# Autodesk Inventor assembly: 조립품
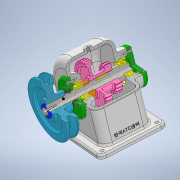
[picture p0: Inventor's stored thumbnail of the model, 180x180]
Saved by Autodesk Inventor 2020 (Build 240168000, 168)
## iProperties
Created: 2022-09
Part Number: 조립품
Document SubType Name: Assembly
Designer: Administrator
Author: Administrator
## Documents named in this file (16)
- C:\Users\Administrator\Desktop\720906V1025\조립품.iam
- C:\Users\Administrator\Desktop\720906V1025\본체.ipt
- C:\Users\Administrator\Desktop\720906V1025\축.ipt
- C:\Users\Administrator\Desktop\720906V1025\뒤커버.ipt
- C:\Users\Administrator\Desktop\720906V1025\베어링 6203.ipt
- C:\Users\Administrator\Desktop\720906V1025\스퍼기어.ipt
- C:\Users\Administrator\Desktop\720906V1025\앞커버.ipt
- C:\Users\Administrator\Desktop\720906V1025\오일 실 17 x 30 x 8.ipt
- C:\Users\Administrator\Desktop\720906V1025\칼라.ipt
- C:\Users\Administrator\Desktop\720906V1025\V-벨트풀리.ipt
- C:\Users\Administrator\Desktop\720906V1025\키 6 x 6 x 22.ipt
- C:\Users\Administrator\Desktop\720906V1025\키 5 x 5 x 18.ipt
- C:\Users\Administrator\Desktop\720906V1025\와셔 6 x 22.ipt
- C:\Users\Administrator\Desktop\720906V1025\육각머리볼트 M3 x 8.ipt
- C:\Users\Administrator\Desktop\720906V1025\멈춤나사 M4 x 10.ipt
- C:\Users\Administrator\Desktop\720906V1025\볼트 M3 x 10.ipt
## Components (9 placed, 2 different names)
1. V-벨트풀리:1 — 플러쉬:1
2. ISO 4762 M3 x 10:2
3. ISO 4762 M3 x 10:3
4. ISO 4762 M3 x 10:4
5. ISO 4762 M3 x 10:5
6. ISO 4762 M3 x 10:1
7. ISO 4762 M3 x 10:6
8. ISO 4762 M3 x 10:7
9. ISO 4762 M3 x 10:8
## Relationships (1: Flush 1)
- 플러쉬:1 [Flush]: V-벨트풀리:1
